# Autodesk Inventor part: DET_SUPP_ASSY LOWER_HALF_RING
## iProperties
Shininess: 64.0
Length Units: 11272
Angle Units: 11279
Time Units: 11290
Mass Units: 11286
Length Display Precision: 3
Angle Display Precision: 2
Compacted: True
Part Number: DET_SUPP_ASSY LOWER_HALF_RING
Document SubType Name: Modeling
Created: 2004-08
Designer: John Blackburn
Manufacturer: Standard
Standards Organization: Custom
Material: Aluminum-6061
Density: 0.0
Volumn: 0.0
Area: 0.0
PropertySet Name: Model Information
Control State: 0
Master: False
Checked Out: False
Author: John Blackburn
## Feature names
1. ExtrusionBlind1
2. AM_HOLE_SI0029_1 [Hole]
3. AM_HOLE_SI0029_2 [Hole]
4. Polar Pattern1 [Circular Pattern]
5. AM_HOLE_SI0029_3 [Hole]
6. AM_HOLE_SI0029_4 [Hole]
7. AM_HOLE_SI0029_5 [Hole]
8. AM_HOLE_SI0029_6 [Hole]
